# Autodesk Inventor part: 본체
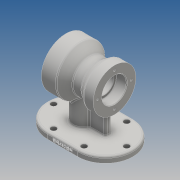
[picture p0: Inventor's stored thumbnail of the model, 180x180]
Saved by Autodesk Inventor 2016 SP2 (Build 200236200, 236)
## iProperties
Created: 2020-01
Part Number: 본체
Material: Generic
Document SubType Name: Modeling
Designer: EZ
Density: 1 g/cm^3
Appearance: Default
Author: EZ
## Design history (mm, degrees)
sketch "스케치1"
  geometry: L1 (-70, -45)-(70, -45); L2 (70, -45)-(70, 45); L3 (70, 45)-(-70, 45); L4 (-70, 45)-(-70, -45); L5 (-70, -45)-(70, 45); L6 (70, -45)-(-70, 45); 1 further point
  constraints: 12 end point, 2 midpoint, 2 parallel, 1 horizontal, 1 perpendicular
  dimensions: "d0" = 140 distance of L3.end L2.end; "d1" = 90 distance of L2.end L1.end
extrude "돌출1" new body sketch "스케치1" distance "d2" = 10; taper "d3" = 0 deg
fillet "모깎기1" dims "d4" = 45
sketch "스케치2"
  geometry: L1 (40, 80)-(-40, 80); L2 (-25, 0)-(-70, 0) reference; L3 (70, 0)-(70, 10) reference; L4 (40, 80)-(40, 120); L5 (40, 120)-(16, 120); L6 (16, 120)-(1.103, 107.5); L7 (-24, 115)-(-40, 115); L8 (-40, 115)-(-40, 80); L9 (1.103, 107.5)-(-13.289, 107.5); L10 (-13.289, 107.5)-(-24, 115); 1 further point
  constraints: 16 end point, 2 horizontal, 2 perpendicular, 1 parallel, 1 vertical
  dimensions: "d5" = 80 distance of L1.start L1.end; "d6" = 80 distance between parallel lines of L2 L1; "d7" = 30 distance from line of L3 L1.start; "d8" = 24 distance from line of L5.end L4; "d10" = 70 diameter of L7 L1; "d12" = 80 diameter of L5 L1; "d14" = 35 deg angle of L9 L10; "d15" = 40 deg angle of L9 L6; "d16" = 55 diameter of L9 L1; "d17" = 16 distance from line of L7.start L8
revolve "회전1" sketch "스케치2" stored, may be unused: angle "d18" = 90 deg
sketch "스케치3"
  geometry: L1 (40, 40)-(40, 120) reference; L2 (-40, 45)-(-40, 115) reference; L3 (40, 80)-(-40, 80); L4 (40, 106)-(20, 106); L5 (20, 106)-(20, 96); L6 (20, 96)-(-23, 96); L7 (-23, 96)-(-23, 100); L8 (-23, 100)-(-40, 100); 1 further point
  constraints: 12 end point, 5 perpendicular, 2 midpoint, 2 point on line
  dimensions: "d19" = 52 diameter of L4 L3; "d20" = 32 diameter of L6 L3; "d21" = 40 diameter of L8 L3; "d22" = 20 distance between parallel lines of L5 L1; "d23" = 17 distance between parallel lines of L2 L7
revolve "회전2" sketch "스케치3" stored, may be unused: angle "d24" = 90 deg
sketch "스케치4"
  geometry: L1 (25, 45)-(-25, 45) reference; L2 (-25, -45)-(25, -45) reference; L3 (-70, 0)-(-72.967, 0); L4 (3.199, 5)-(30, 5); L5 (30, 5)-(30, -5); L6 (30, -5)-(3.199, -5); L7 (40, 35)-(40, -35) reference; A1 r 16 centre (-12, 0) between (3.199, 5) and (3.199, -5); A2 r 45 centre (-25, 0) between (-25, 45) and (-25, -45) reference; A3 r 45 centre (25, 0) between (25, -45) and (25, 45) reference; 1 further point
  constraints: 8 end point, 3 point on circle, 2 horizontal, 2 perpendicular, 1 centre point, 1 horizontal alignment, 1 parallel
  dimensions: "d25" = 32 diameter of A1; "d26" = 58 distance of A1.centre L3.start; "d27" = 10 distance between parallel lines of L6 L4; "d79" = 10 distance between parallel lines of L5 L7
extrude "돌출2" join sketch "스케치4" stored distance "d29" = 10; taper "d30" = 0 deg
sketch "스케치5"
  geometry: C1 r 26 at (0, 0) reference; C2 r 40 at (0, 0) reference; 2 further points
  constraints: 1 horizontal alignment
  dimensions: "d31" = 33 distance of C1.centre point (33, 0)
hole "구멍1" sketch "스케치5" at (33, 0) diameter "d32" = 3.242; stored, may be unused: countersink angle "d36" = 90 deg, drill point angle "d38" = 118 deg; dims "d33" = 9, "d34" = 4, "d35" = 2, "d37" = 11
sketch "스케치6"
  geometry: C1 r 20 at (0, 0) reference; C2 r 35 at (0, 0) reference; 2 further points
  constraints: 1 horizontal alignment
  dimensions: "d42" = 27.5 distance of C1.centre point (-27.5, 0)
hole "구멍2" sketch "스케치6" at (-27.5, 0) diameter "d43" = 3.242; stored, may be unused: countersink angle "d47" = 90 deg, drill point angle "d49" = 118 deg; dims "d44" = 9, "d45" = 4, "d46" = 2, "d48" = 11
sketch "스케치7"
  geometry: L1 (25, 45)-(-25, 45) reference; L2 (-25, -45)-(25, -45) reference; L3 (-25, 35)-(25, 35); L4 (25, -35)-(-25, -35); C1 r 4.5 at (-60, 0); C2 r 4.5 at (-25, 35); C3 r 4.5 at (-25, -35); C4 r 4.5 at (25, 35); C5 r 4.5 at (25, -35); C6 r 4.5 at (60, 0); A1 r 45 centre (-25, 0) between (-25, 45) and (-25, -45) reference; A2 r 45 centre (25, 0) between (25, -45) and (25, 45) reference; A3 r 35 centre (-25, 0) between (-25, 35) and (-25, -35); A4 r 35 centre (25, 0) between (25, -35) and (25, 35); 1 further point
  constraints: 8 centre point, 6 point on circle, 4 coincident, 4 end point, 3 other
  dimensions: "d54" = 10 radial gap between concentric circles of A1 A3; "d55" = 9 diameter of C1; "d56" = 9 diameter of C2; "d57" = 9 diameter of C3; "d58" = 9 diameter of C4; "d59" = 9 diameter of C5; "d60" = 9 diameter of C6
extrude "돌출3" cut sketch "스케치7" distance "d61" = 10; taper "d62" = 0 deg
fillet "모깎기5" dims "d66" = 3
fillet "모깎기6" dims "d67" = 3
fillet "모깎기7" dims "d68" = 3
fillet "모깎기8" dims "d69" = 3
sketch "스케치8"
  geometry: L1 (-45, 0)-(-45, 7) reference; 2 further points
  constraints: 1 other
  dimensions: "d70" = 4 distance of point (25, 0) point (25, 4); "d71" = 70 distance from line of point (25, 4) L1
feature "엠보싱1" sketch "스케치8" dims "d0" = 140, "d1" = 90, "d5" = 80, "d6" = 80, "d7" = 30, "d8" = 24, "d10" = 70, "d12" = 80, "d14" = 35 deg, "d15" = 40 deg, "d16" = 55, "d17" = 16, "d72" = 0.5, "d73" = 0
fillet "모깎기9" dims "d74" = 3
fillet "모깎기10" dims "d75" = 0.3
chamfer "모따기1" distance "d76" = 1; stored, may be unused: second distance "d77" = 2, angle "d78" = 45 deg
node "솔리드1"
pattern_circular "원형 패턴1" dims angle "d40" = 360 deg
pattern_circular "원형 패턴2" dims angle "d51" = 360 deg
node "투영된 루프1"
node "투영된 루프2"
node "투영된 루프3"
node "투영된 루프4"
